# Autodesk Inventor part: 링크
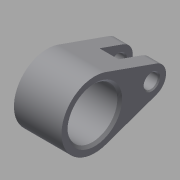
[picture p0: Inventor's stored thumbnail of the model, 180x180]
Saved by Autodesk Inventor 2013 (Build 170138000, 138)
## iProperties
Created: 2016-08
Part Number: 링크
Material: 강철, 탄소
Document SubType Name: Modeling
Designer: mduedu
Density: 7.87 g/cm^3
Author: mduedu
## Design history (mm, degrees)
sketch "스케치1"
  geometry: L1 (26, 5.657)-(4.667, 13.199); L2 (26, -5.657)-(4.667, -13.199); C1 r 10.5 at (0, 0); C2 r 3 at (24, 0); A1 r 14 centre (0, 0) between (4.667, 13.199) and (4.667, -13.199); A2 r 6 centre (24, 0) between (26, 5.657) and (26, -5.657); 1 further point
  constraints: 4 centre point, 4 end point, 4 point on circle, 4 tangent, 3 coincident, 1 horizontal alignment
  dimensions: "d0" = 28 diameter of A1; "d2" = 12 diameter of A2; "d3" = 24 distance of A2.centre point (0, 0); "d4" = 21 diameter of C1; "d5" = 6 diameter of C2
extrude "돌출1" new body sketch "스케치1" stored distance "d6" = 20; taper "d7" = 0 deg
sketch "스케치2"
  geometry: L1 (-10, 30)-(10, 30) reference; L2 (0, 0)-(0, 30); L3 (-4, 30)-(4, 30); L4 (4, 30)-(4, 16); L5 (4, 16)-(-4, 16); L6 (-4, 16)-(-4, 30)
  constraints: 10 end point, 2 midpoint, 2 parallel, 1 horizontal, 1 perpendicular, 1 point on line
  dimensions: "d8" = 8 distance between parallel lines of L4 L6; "d10" = 14 distance of L3.end L4.end
extrude "돌출2" cut sketch "스케치2" stored distance "d11" = 20; taper "d12" = 0 deg
chamfer "모따기1" distance "d13" = 1; stored, may be unused: second distance "d14" = 2, angle "d15" = 45 deg
chamfer "모따기2" distance "d16" = 0.5; stored, may be unused: second distance "d17" = 2, angle "d18" = 45 deg
node "솔리드1"
